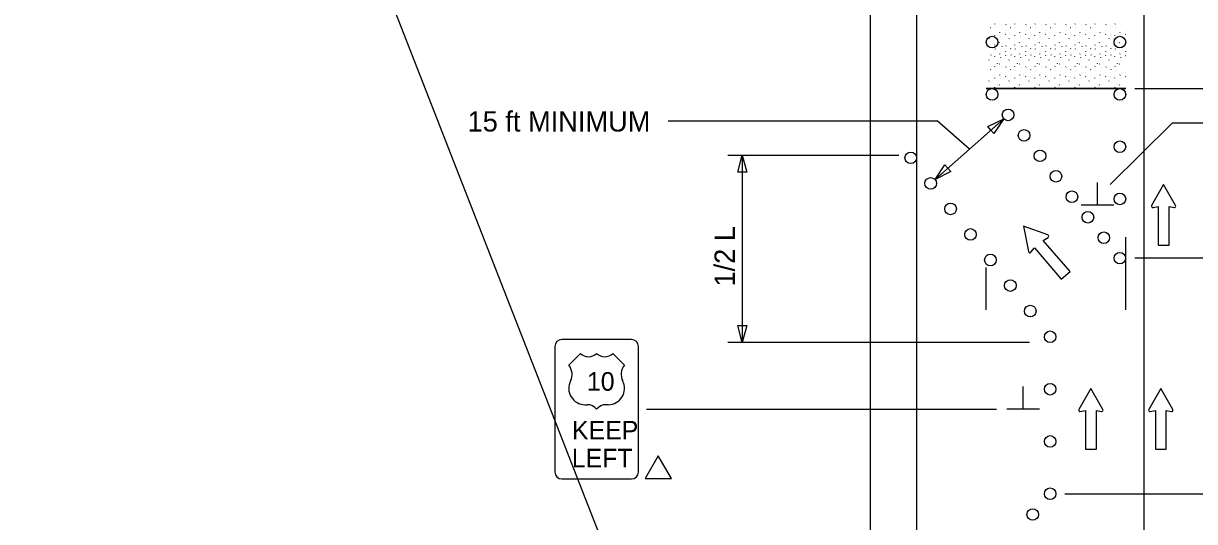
# Model space of a CAD drawing. Extents: x 16512 to 19512, y 5761 to 6974.
# Drawn here: x 16595 to 16998.2, y 6297.4 to 6469 of the extents above; entities that cross this region are included whole.
import ezdxf

# ---------------------------------------------------------------- set-up
doc = ezdxf.new("R2010")
doc.units = 0
for name, color, linetype in [('ALI_LEGAL_EX', 7, 'Continuous'), ('MT_SCRATCH_LEVEL_A', 7, 'Continuous'), ('MT_SCRATCH_LEVEL_E', 7, 'Continuous'), ('PAVT_EDGE_EX', 7, 'Continuous'), ('TRAFFIC_SIGNS_PR', 7, 'Continuous'), ('TYPICAL_EX', 7, 'Continuous'), ('TYPICAL_TEXT_DIMEN_PR', 7, 'Continuous')]:
    doc.layers.add(name, color=color, linetype=linetype)

msp = doc.modelspace()

# ---------------------------------------------------------------- linework, layer by layer
at = {"layer": 'ALI_LEGAL_EX'}
for p, q in [((16980.68, 6974.12), (16980.68, 6155.98)), ((16980.68, 6922.21), (16980.68, 6058.3)), ((16594.98, 6800.51), (16817, 6232.14))]:
    msp.add_line(p, q, dxfattribs=at)
for points in [[(16974.45, 6370.33), (16974.45, 6395.33)], [(16926.45, 6370.33), (16926.45, 6384.97)]]:
    msp.add_lwpolyline(points, dxfattribs=at)
at = {"layer": 'MT_SCRATCH_LEVEL_A'}
for p, q in [((16927.94, 6467.62), (16927.99, 6467.55)), ((16929.39, 6468.75), (16929.44, 6468.87)), ((16929.47, 6467.49), (16929.53, 6467.41)), ((16931.76, 6468.3), (16931.81, 6468.23)), ((16933.21, 6468.45), (16933.26, 6468.57)), ((16934.83, 6467.62), (16934.88, 6467.55)), ((16936.28, 6468.75), (16936.33, 6468.87)), ((16936.36, 6467.49), (16936.41, 6467.41)), ((16938.65, 6468.3), (16938.7, 6468.23)), ((16940.1, 6468.45), (16940.15, 6468.57)), ((16941.72, 6467.62), (16941.77, 6467.55)), ((16943.17, 6468.75), (16943.22, 6468.87)), ((16943.25, 6467.49), (16943.3, 6467.41)), ((16945.54, 6468.3), (16945.59, 6468.23)), ((16946.99, 6468.45), (16947.04, 6468.57)), ((16948.61, 6467.62), (16948.66, 6467.55)), ((16950.06, 6468.75), (16950.11, 6468.87)), ((16950.14, 6467.49), (16950.19, 6467.41)), ((16952.42, 6468.3), (16952.48, 6468.23)), ((16953.88, 6468.45), (16953.93, 6468.57)), ((16955.49, 6467.62), (16955.55, 6467.55)), ((16956.94, 6468.75), (16956.99, 6468.87)), ((16957.02, 6467.49), (16957.08, 6467.41)), ((16959.31, 6468.3), (16959.37, 6468.23)), ((16960.76, 6468.45), (16960.81, 6468.57)), ((16962.38, 6467.62), (16962.43, 6467.55)), ((16963.83, 6468.75), (16963.88, 6468.87)), ((16963.91, 6467.49), (16963.96, 6467.41)), ((16966.2, 6468.3), (16966.25, 6468.23)), ((16967.65, 6468.45), (16967.7, 6468.57)), ((16969.27, 6467.62), (16969.32, 6467.55)), ((16970.72, 6468.75), (16970.77, 6468.87)), ((16970.8, 6467.49), (16970.85, 6467.41)), ((16973.09, 6468.3), (16973.14, 6468.23)), ((16927.37, 6463.66), (16927.42, 6463.78)), ((16927.99, 6465.42), (16928.04, 6465.34)), ((16929.27, 6464.84), (16929.29, 6464.72)), ((16931.12, 6465.7), (16931.17, 6465.81)), ((16931.3, 6464.5), (16931.35, 6464.42)), ((16933.04, 6466.57), (16933.09, 6466.49)), ((16933.08, 6465.16), (16933.13, 6465.28)), ((16934.26, 6463.66), (16934.31, 6463.78)), ((16934.88, 6465.42), (16934.93, 6465.34)), ((16936.16, 6464.84), (16936.17, 6464.72)), ((16938, 6465.7), (16938.05, 6465.81)), ((16938.19, 6464.5), (16938.24, 6464.42)), ((16939.93, 6466.57), (16939.98, 6466.49)), ((16939.97, 6465.16), (16940.02, 6465.28)), ((16941.15, 6463.66), (16941.2, 6463.78)), ((16941.77, 6465.42), (16941.82, 6465.34)), ((16943.05, 6464.84), (16943.06, 6464.72)), ((16944.89, 6465.7), (16944.94, 6465.81)), ((16945.08, 6464.5), (16945.13, 6464.42)), ((16946.81, 6466.57), (16946.87, 6466.49)), ((16946.86, 6465.16), (16946.91, 6465.28)), ((16948.04, 6463.66), (16948.09, 6463.78)), ((16948.65, 6465.42), (16948.71, 6465.34)), ((16949.94, 6464.84), (16949.95, 6464.72)), ((16951.78, 6465.7), (16951.83, 6465.81)), ((16951.97, 6464.5), (16952.02, 6464.42)), ((16953.7, 6466.57), (16953.75, 6466.49)), ((16953.74, 6465.16), (16953.8, 6465.28)), ((16954.92, 6463.66), (16954.97, 6463.78)), ((16955.54, 6465.42), (16955.59, 6465.34)), ((16956.82, 6464.84), (16956.84, 6464.72)), ((16958.67, 6465.7), (16958.72, 6465.81)), ((16958.85, 6464.5), (16958.9, 6464.42)), ((16960.59, 6466.57), (16960.64, 6466.49)), ((16960.63, 6465.16), (16960.69, 6465.28)), ((16961.81, 6463.66), (16961.86, 6463.78)), ((16962.43, 6465.42), (16962.48, 6465.34)), ((16963.71, 6464.84), (16963.72, 6464.72)), ((16965.55, 6465.7), (16965.6, 6465.81)), ((16965.74, 6464.5), (16965.79, 6464.42)), ((16967.48, 6466.57), (16967.53, 6466.49)), ((16967.52, 6465.16), (16967.57, 6465.28)), ((16968.7, 6463.66), (16968.75, 6463.78)), ((16969.32, 6465.42), (16969.37, 6465.34)), ((16970.6, 6464.84), (16970.61, 6464.72)), ((16972.44, 6465.7), (16972.49, 6465.81)), ((16972.63, 6464.5), (16972.68, 6464.42)), ((16974.37, 6466.57), (16974.42, 6466.49)), ((16974.41, 6465.16), (16974.45, 6465.25)), ((16929.39, 6461.47), (16929.44, 6461.58)), ((16929.47, 6460.2), (16929.53, 6460.12)), ((16930.16, 6462.43), (16930.21, 6462.35)), ((16930.89, 6462.4), (16930.95, 6462.32)), ((16931.76, 6461.02), (16931.81, 6460.94)), ((16933.04, 6459.28), (16933.09, 6459.2)), ((16933.21, 6461.17), (16933.26, 6461.28)), ((16934.83, 6460.34), (16934.88, 6460.26)), ((16936.28, 6461.47), (16936.33, 6461.58)), ((16936.36, 6460.2), (16936.41, 6460.12)), ((16937.05, 6462.43), (16937.1, 6462.35)), ((16937.78, 6462.4), (16937.83, 6462.32)), ((16938.65, 6461.02), (16938.7, 6460.94)), ((16939.93, 6459.28), (16939.98, 6459.2)), ((16940.1, 6461.17), (16940.15, 6461.28)), ((16941.72, 6460.34), (16941.77, 6460.26)), ((16943.17, 6461.47), (16943.22, 6461.58)), ((16943.25, 6460.2), (16943.3, 6460.12)), ((16943.93, 6462.43), (16943.98, 6462.35)), ((16944.67, 6462.4), (16944.72, 6462.32)), ((16945.54, 6461.02), (16945.59, 6460.94)), ((16946.81, 6459.28), (16946.87, 6459.2)), ((16946.99, 6461.17), (16947.04, 6461.28)), ((16948.61, 6460.34), (16948.66, 6460.26)), ((16950.06, 6461.47), (16950.11, 6461.58)), ((16950.14, 6460.2), (16950.19, 6460.12)), ((16950.82, 6462.43), (16950.87, 6462.35)), ((16951.56, 6462.4), (16951.61, 6462.32)), ((16952.42, 6461.02), (16952.48, 6460.94)), ((16953.7, 6459.28), (16953.75, 6459.2)), ((16953.88, 6461.17), (16953.93, 6461.28)), ((16955.49, 6460.34), (16955.55, 6460.26)), ((16956.94, 6461.47), (16956.99, 6461.58)), ((16957.02, 6460.2), (16957.08, 6460.12)), ((16957.71, 6462.43), (16957.76, 6462.35)), ((16958.44, 6462.4), (16958.5, 6462.32)), ((16959.31, 6461.02), (16959.37, 6460.94)), ((16960.59, 6459.28), (16960.64, 6459.2)), ((16960.76, 6461.17), (16960.81, 6461.28)), ((16962.38, 6460.34), (16962.43, 6460.26)), ((16963.83, 6461.47), (16963.88, 6461.58)), ((16963.91, 6460.2), (16963.96, 6460.12)), ((16964.6, 6462.43), (16964.65, 6462.35)), ((16965.33, 6462.4), (16965.38, 6462.32)), ((16966.2, 6461.02), (16966.25, 6460.94)), ((16967.48, 6459.28), (16967.53, 6459.2)), ((16967.65, 6461.17), (16967.7, 6461.28)), ((16969.27, 6460.34), (16969.32, 6460.26)), ((16970.72, 6461.47), (16970.77, 6461.58)), ((16970.8, 6460.2), (16970.85, 6460.12)), ((16971.48, 6462.43), (16971.53, 6462.35)), ((16972.22, 6462.4), (16972.27, 6462.32)), ((16973.09, 6461.02), (16973.14, 6460.94)), ((16974.37, 6459.28), (16974.42, 6459.2)), ((16927.37, 6456.38), (16927.42, 6456.49)), ((16927.99, 6458.13), (16928.04, 6458.05)), ((16929.27, 6457.56), (16929.29, 6457.44)), ((16930.16, 6455.14), (16930.21, 6455.06)), ((16930.89, 6455.11), (16930.95, 6455.03)), ((16931.12, 6458.41), (16931.17, 6458.53)), ((16931.3, 6457.21), (16931.35, 6457.13)), ((16933.08, 6457.88), (16933.13, 6458)), ((16934.26, 6456.38), (16934.31, 6456.49)), ((16934.88, 6458.13), (16934.93, 6458.05)), ((16936.16, 6457.56), (16936.17, 6457.44)), ((16937.05, 6455.14), (16937.1, 6455.06)), ((16937.78, 6455.11), (16937.83, 6455.03)), ((16938, 6458.41), (16938.05, 6458.53)), ((16938.19, 6457.21), (16938.24, 6457.13)), ((16939.97, 6457.88), (16940.02, 6458)), ((16941.15, 6456.38), (16941.2, 6456.49)), ((16941.77, 6458.13), (16941.82, 6458.05)), ((16943.05, 6457.56), (16943.06, 6457.44)), ((16943.93, 6455.14), (16943.98, 6455.06)), ((16944.67, 6455.11), (16944.72, 6455.03)), ((16944.89, 6458.41), (16944.94, 6458.53)), ((16945.08, 6457.21), (16945.13, 6457.13)), ((16946.86, 6457.88), (16946.91, 6458)), ((16948.04, 6456.38), (16948.09, 6456.49)), ((16948.65, 6458.13), (16948.71, 6458.05)), ((16949.94, 6457.56), (16949.95, 6457.44)), ((16950.82, 6455.14), (16950.87, 6455.06)), ((16951.56, 6455.11), (16951.61, 6455.03)), ((16951.78, 6458.41), (16951.83, 6458.53)), ((16951.97, 6457.21), (16952.02, 6457.13)), ((16953.74, 6457.88), (16953.8, 6458)), ((16954.92, 6456.38), (16954.97, 6456.49)), ((16955.54, 6458.13), (16955.59, 6458.05)), ((16956.82, 6457.56), (16956.84, 6457.44)), ((16957.71, 6455.14), (16957.76, 6455.06)), ((16958.44, 6455.11), (16958.5, 6455.03)), ((16958.67, 6458.41), (16958.72, 6458.53)), ((16958.85, 6457.21), (16958.9, 6457.13)), ((16960.63, 6457.88), (16960.69, 6458)), ((16961.81, 6456.38), (16961.86, 6456.49)), ((16962.43, 6458.13), (16962.48, 6458.05)), ((16963.71, 6457.56), (16963.72, 6457.44)), ((16964.6, 6455.14), (16964.65, 6455.06)), ((16965.33, 6455.11), (16965.38, 6455.03)), ((16965.55, 6458.41), (16965.6, 6458.53)), ((16965.74, 6457.21), (16965.79, 6457.13)), ((16967.52, 6457.88), (16967.57, 6458)), ((16968.7, 6456.38), (16968.75, 6456.49)), ((16969.32, 6458.13), (16969.37, 6458.05)), ((16970.6, 6457.56), (16970.61, 6457.44)), ((16971.48, 6455.14), (16971.53, 6455.06)), ((16972.22, 6455.11), (16972.27, 6455.03)), ((16972.44, 6458.41), (16972.49, 6458.53)), ((16972.63, 6457.21), (16972.68, 6457.13)), ((16974.41, 6457.88), (16974.45, 6457.97)), ((16927.94, 6453.06), (16927.99, 6452.98)), ((16927.99, 6450.85), (16928.04, 6450.77)), ((16929.39, 6454.18), (16929.44, 6454.3)), ((16929.47, 6452.91), (16929.53, 6452.84)), ((16931.12, 6451.13), (16931.17, 6451.24)), ((16931.76, 6453.73), (16931.81, 6453.65)), ((16933.04, 6452), (16933.09, 6451.92)), ((16933.21, 6453.88), (16933.26, 6454)), ((16934.83, 6453.06), (16934.88, 6452.98)), ((16934.88, 6450.85), (16934.93, 6450.77)), ((16936.28, 6454.18), (16936.33, 6454.3)), ((16936.36, 6452.91), (16936.41, 6452.84)), ((16938, 6451.13), (16938.05, 6451.24)), ((16938.65, 6453.73), (16938.7, 6453.65)), ((16939.93, 6452), (16939.98, 6451.92)), ((16940.1, 6453.88), (16940.15, 6454)), ((16941.72, 6453.06), (16941.77, 6452.98)), ((16941.77, 6450.85), (16941.82, 6450.77)), ((16943.17, 6454.18), (16943.22, 6454.3)), ((16943.25, 6452.91), (16943.3, 6452.84)), ((16944.89, 6451.13), (16944.94, 6451.24)), ((16945.54, 6453.73), (16945.59, 6453.65)), ((16946.81, 6452), (16946.87, 6451.92)), ((16946.99, 6453.88), (16947.04, 6454)), ((16948.61, 6453.06), (16948.66, 6452.98)), ((16948.65, 6450.85), (16948.71, 6450.77)), ((16950.06, 6454.18), (16950.11, 6454.3)), ((16950.14, 6452.91), (16950.19, 6452.84)), ((16951.78, 6451.13), (16951.83, 6451.24)), ((16952.42, 6453.73), (16952.48, 6453.65)), ((16953.7, 6452), (16953.75, 6451.92)), ((16953.88, 6453.88), (16953.93, 6454)), ((16955.49, 6453.06), (16955.55, 6452.98)), ((16955.54, 6450.85), (16955.59, 6450.77)), ((16956.94, 6454.18), (16956.99, 6454.3)), ((16957.02, 6452.91), (16957.08, 6452.84)), ((16958.67, 6451.13), (16958.72, 6451.24)), ((16959.31, 6453.73), (16959.37, 6453.65)), ((16960.59, 6452), (16960.64, 6451.92)), ((16960.76, 6453.88), (16960.81, 6454)), ((16962.38, 6453.06), (16962.43, 6452.98)), ((16962.43, 6450.85), (16962.48, 6450.77)), ((16963.83, 6454.18), (16963.88, 6454.3)), ((16963.91, 6452.91), (16963.96, 6452.84)), ((16965.55, 6451.13), (16965.6, 6451.24)), ((16966.2, 6453.73), (16966.25, 6453.65)), ((16967.48, 6452), (16967.53, 6451.92)), ((16967.65, 6453.88), (16967.7, 6454)), ((16969.27, 6453.06), (16969.32, 6452.98)), ((16969.32, 6450.85), (16969.37, 6450.77)), ((16970.72, 6454.18), (16970.77, 6454.3)), ((16970.8, 6452.91), (16970.85, 6452.84)), ((16972.44, 6451.13), (16972.49, 6451.24)), ((16973.09, 6453.73), (16973.14, 6453.65)), ((16974.37, 6452), (16974.42, 6451.92)), ((16927.37, 6449.09), (16927.42, 6449.21)), ((16929.27, 6450.27), (16929.29, 6450.15)), ((16929.39, 6446.9), (16929.44, 6447.01)), ((16930.16, 6447.86), (16930.21, 6447.78)), ((16930.89, 6447.83), (16930.95, 6447.75)), ((16931.3, 6449.93), (16931.35, 6449.85)), ((16933.08, 6450.6), (16933.13, 6450.71)), ((16934.26, 6449.09), (16934.31, 6449.21)), ((16936.16, 6450.27), (16936.17, 6450.15)), ((16936.28, 6446.9), (16936.33, 6447.01)), ((16937.05, 6447.86), (16937.1, 6447.78)), ((16937.78, 6447.83), (16937.83, 6447.75)), ((16938.19, 6449.93), (16938.24, 6449.85)), ((16939.97, 6450.6), (16940.02, 6450.71)), ((16941.15, 6449.09), (16941.2, 6449.21)), ((16943.05, 6450.27), (16943.06, 6450.15)), ((16943.17, 6446.9), (16943.22, 6447.01)), ((16943.93, 6447.86), (16943.98, 6447.78)), ((16944.67, 6447.83), (16944.72, 6447.75)), ((16945.08, 6449.93), (16945.13, 6449.85)), ((16946.86, 6450.6), (16946.91, 6450.71)), ((16948.04, 6449.09), (16948.09, 6449.21)), ((16949.94, 6450.27), (16949.95, 6450.15)), ((16950.06, 6446.9), (16950.11, 6447.01)), ((16950.82, 6447.86), (16950.87, 6447.78)), ((16951.56, 6447.83), (16951.61, 6447.75)), ((16951.97, 6449.93), (16952.02, 6449.85)), ((16953.74, 6450.6), (16953.8, 6450.71)), ((16954.92, 6449.09), (16954.97, 6449.21)), ((16956.82, 6450.27), (16956.84, 6450.15)), ((16956.94, 6446.9), (16956.99, 6447.01)), ((16957.71, 6447.86), (16957.76, 6447.78)), ((16958.44, 6447.83), (16958.5, 6447.75)), ((16958.85, 6449.93), (16958.9, 6449.85)), ((16960.63, 6450.6), (16960.69, 6450.71)), ((16961.81, 6449.09), (16961.86, 6449.21)), ((16963.71, 6450.27), (16963.72, 6450.15)), ((16963.83, 6446.9), (16963.88, 6447.01)), ((16964.6, 6447.86), (16964.65, 6447.78)), ((16965.33, 6447.83), (16965.38, 6447.75)), ((16965.74, 6449.93), (16965.79, 6449.85)), ((16967.52, 6450.6), (16967.57, 6450.71)), ((16968.7, 6449.09), (16968.75, 6449.21)), ((16970.6, 6450.27), (16970.61, 6450.15)), ((16970.72, 6446.9), (16970.77, 6447.01)), ((16971.48, 6447.86), (16971.53, 6447.78)), ((16972.22, 6447.83), (16972.27, 6447.75)), ((16972.63, 6449.93), (16972.68, 6449.85)), ((16974.41, 6450.6), (16974.45, 6450.68)), ((16974.45, 6446.53), (16926.45, 6446.53)), ((16926.45, 6446.53), (16974.45, 6446.53)), ((16933.21, 6446.6), (16933.26, 6446.72)), ((16940.1, 6446.6), (16940.15, 6446.72)), ((16946.99, 6446.6), (16947.04, 6446.72)), ((16953.88, 6446.6), (16953.93, 6446.72)), ((16960.76, 6446.6), (16960.81, 6446.72)), ((16967.65, 6446.6), (16967.7, 6446.72))]:
    msp.add_line(p, q, dxfattribs=at)
at = {"layer": 'MT_SCRATCH_LEVEL_E'}
for p, q in [((16987.48, 6413.53), (16983.37, 6406.28)), ((16991.62, 6406.28), (16987.48, 6413.53)), ((16983.85, 6405.6), (16985.63, 6405.92)), ((16985.63, 6405.92), (16985.63, 6392.66)), ((16989.37, 6392.66), (16989.37, 6405.92)), ((16989.37, 6405.92), (16991.15, 6405.6)), ((16985.63, 6392.66), (16989.37, 6392.66)), ((16962.45, 6343.28), (16958.33, 6336.04)), ((16962.45, 6343.28), (16958.33, 6336.04)), ((16966.59, 6336.04), (16962.45, 6343.28)), ((16966.59, 6336.04), (16962.45, 6343.28)), ((16986.5, 6343.28), (16982.39, 6336.04)), ((16986.5, 6343.28), (16982.39, 6336.04)), ((16990.65, 6336.04), (16986.5, 6343.28)), ((16990.65, 6336.04), (16986.5, 6343.28)), ((16958.82, 6335.36), (16960.59, 6335.67)), ((16958.82, 6335.36), (16960.59, 6335.67)), ((16960.59, 6335.67), (16960.59, 6322.41)), ((16960.59, 6335.67), (16960.59, 6322.41)), ((16964.34, 6322.41), (16964.34, 6335.67)), ((16964.34, 6335.67), (16966.11, 6335.36)), ((16964.34, 6322.41), (16964.34, 6335.67)), ((16964.34, 6335.67), (16966.11, 6335.36)), ((16982.87, 6335.36), (16984.65, 6335.67)), ((16982.87, 6335.36), (16984.65, 6335.67)), ((16984.65, 6335.67), (16984.65, 6322.41)), ((16984.65, 6335.67), (16984.65, 6322.41)), ((16988.39, 6322.41), (16988.39, 6335.67)), ((16988.39, 6335.67), (16990.17, 6335.36)), ((16988.39, 6322.41), (16988.39, 6335.67)), ((16988.39, 6335.67), (16990.17, 6335.36)), ((16960.59, 6322.41), (16964.34, 6322.41)), ((16960.59, 6322.41), (16964.34, 6322.41)), ((16984.65, 6322.41), (16988.39, 6322.41)), ((16984.65, 6322.41), (16988.39, 6322.41))]:
    msp.add_line(p, q, dxfattribs=at)
for centre, start, end in [((16983.77, 6406.06), 150.4248, 279.9638), ((16991.22, 6406.06), 260.0362, 29.7731), ((16958.74, 6335.81), 150.4248, 279.9638), ((16958.74, 6335.81), 150.4248, 279.9638), ((16966.18, 6335.81), 260.0362, 29.7731), ((16966.18, 6335.81), 260.0362, 29.7731), ((16982.8, 6335.81), 150.4248, 279.9638), ((16982.8, 6335.81), 150.4248, 279.9638), ((16990.24, 6335.81), 260.0362, 29.7731), ((16990.24, 6335.81), 260.0362, 29.7731)]:
    msp.add_arc(centre, 0.463, start, end, dxfattribs=at)
at = {"layer": 'PAVT_EDGE_EX'}
for p, q in [((16886.45, 6480.53), (16886.45, 6125.9)), ((16902.45, 6480.53), (16902.45, 6125.9))]:
    msp.add_line(p, q, dxfattribs=at)
at = {"layer": 'TRAFFIC_SIGNS_PR'}
for p, q in [((16804.31, 6360.11), (16780.31, 6360.11)), ((16777.91, 6357.71), (16777.91, 6314.51)), ((16806.71, 6314.51), (16806.71, 6357.71)), ((16780.31, 6312.11), (16804.31, 6312.11))]:
    msp.add_line(p, q, dxfattribs=at)
for centre in [(16928.45, 6462.53), (16972.44, 6462.53), (16928.45, 6444.53), (16928.45, 6444.53), (16972.44, 6444.53), (16933.95, 6437.48), (16939.44, 6430.43), (16972.44, 6426.53), (16900.45, 6422.7), (16944.94, 6423.38), (16907.3, 6413.9), (16950.43, 6416.34), (16955.93, 6409.29), (16972.44, 6408.53), (16914.16, 6405.11), (16961.42, 6402.24), (16921.02, 6396.31), (16966.92, 6395.19), (16927.87, 6387.52), (16972.42, 6388.14), (16934.73, 6378.72), (16941.59, 6369.93), (16948.44, 6361.08), (16948.44, 6343.03), (16948.44, 6325.03), (16948.44, 6307.03), (16942.44, 6299.89)]:
    msp.add_circle(centre, 2, dxfattribs=at)
for centre, start, end in [((16780.31, 6357.71), 90, 180), ((16804.31, 6357.71), 0, 90), ((16780.31, 6314.51), 180, 270), ((16804.31, 6314.51), 270, 0)]:
    msp.add_arc(centre, 2.4, start, end, dxfattribs=at)
at = {"layer": 'TYPICAL_EX'}
for p, q in [((16782.71, 6351.31), (16786.71, 6355.31)), ((16801.91, 6351.31), (16797.91, 6355.31)), ((16788.3, 6337.7), (16789.1, 6337.7)), ((16796.31, 6337.7), (16795.51, 6337.7))]:
    msp.add_line(p, q, dxfattribs=at)
for centre, radius, start, end in [((16789.51, 6358.22), 4.04, 226.1404, 313.8596), ((16795.11, 6358.22), 4.04, 226.1404, 313.8596), ((16778.92, 6348.1), 4.96, 333.0977, 40.1936), ((16805.7, 6348.1), 4.96, 139.8064, 206.9023), ((16788.31, 6343.29), 5.59, 152.6698, 269.9013), ((16796.3, 6343.29), 5.59, 270.0987, 27.3302), ((16789.11, 6333.69), 4.01, 37.1038, 90.1385), ((16795.5, 6333.69), 4.01, 89.8615, 142.8962)]:
    msp.add_arc(centre, radius, start, end, dxfattribs=at)
at = {"layer": 'TYPICAL_TEXT_DIMEN_PR'}
for p, q in [((16977.64, 6446.53), (17063.45, 6446.53)), ((16816.88, 6435.45), (16909.5, 6435.45)), ((16932.45, 6436.16), (16908.8, 6415.23)), ((16920.63, 6425.69), (16909.5, 6435.45)), ((16927.02, 6433.45), (16932.45, 6436.16)), ((16932.45, 6436.16), (16929.1, 6431.1)), ((16969.12, 6413.48), (16990.46, 6434.68)), ((17054.35, 6434.68), (16990.46, 6434.68)), ((16928.06, 6432.27), (16927.02, 6433.45)), ((16929.1, 6431.1), (16928.06, 6432.27)), ((16837.45, 6423.59), (16896.35, 6423.59)), ((16840.88, 6417.73), (16842.45, 6423.59)), ((16842.45, 6423.59), (16842.45, 6359.08)), ((16842.45, 6423.59), (16844.02, 6417.73)), ((16908.8, 6415.23), (16912.15, 6420.29)), ((16912.15, 6420.29), (16913.19, 6419.11)), ((16913.19, 6419.11), (16914.23, 6417.94)), ((16842.45, 6417.73), (16840.88, 6417.73)), ((16844.02, 6417.73), (16842.45, 6417.73)), ((16914.23, 6417.94), (16908.8, 6415.23)), ((16964.72, 6406.41), (16964.72, 6414.19)), ((16970.35, 6406.41), (16959.1, 6406.41)), ((16947.63, 6396.15), (16939.24, 6399.11)), ((16939.24, 6399.11), (16940.96, 6390.4)), ((16946.07, 6394.28), (16947.72, 6395.26)), ((16941.83, 6390.18), (16943.04, 6391.67)), ((16943.04, 6391.67), (16952.27, 6380.96)), ((16955.3, 6383.57), (16946.07, 6394.28)), ((17093.24, 6388.14), (16977.64, 6388.14)), ((16952.27, 6380.96), (16955.3, 6383.57)), ((16842.45, 6359.08), (16840.88, 6364.94)), ((16840.88, 6364.94), (16842.45, 6364.94)), ((16842.45, 6364.94), (16844.02, 6364.94)), ((16844.02, 6364.94), (16842.45, 6359.08)), ((16941.33, 6359.08), (16837.45, 6359.08)), ((16939.2, 6336.14), (16939.2, 6343.92)), ((16809.51, 6336.14), (16929.95, 6336.14)), ((16944.82, 6336.14), (16933.57, 6336.14)), ((16953.49, 6307.03), (17093.24, 6307.03))]:
    msp.add_line(p, q, dxfattribs=at)
msp.add_lwpolyline([(16813.53, 6320.07), (16809, 6312.23), (16818.06, 6312.23)], close=True, dxfattribs=at)
for centre, start, end in [((16947.46, 6395.68), 300.7803, 70.5173), ((16941.45, 6390.5), 191.169, 320.708)]:
    msp.add_arc(centre, 0.494, start, end, dxfattribs=at)

# ---------------------------------------------------------------- texts
at = {"layer": 'TRAFFIC_SIGNS_PR'}
for s, p in [('10', (16788.97, 6342.51)), ('KEEP', (16783.84, 6325.71)), ('LEFT', (16783.76, 6316.11))]:
    msp.add_text(s, height=6.4, dxfattribs=at).set_placement(p)
at = {"layer": 'TYPICAL_TEXT_DIMEN_PR'}
msp.add_text('15 ft MINIMUM', height=7, dxfattribs=at).set_placement((16747.88, 6431.75))
msp.add_text('1/2 L', height=7, rotation=90, dxfattribs=at).set_placement((16839.89, 6378.38))

doc.saveas('drawing.dxf')
